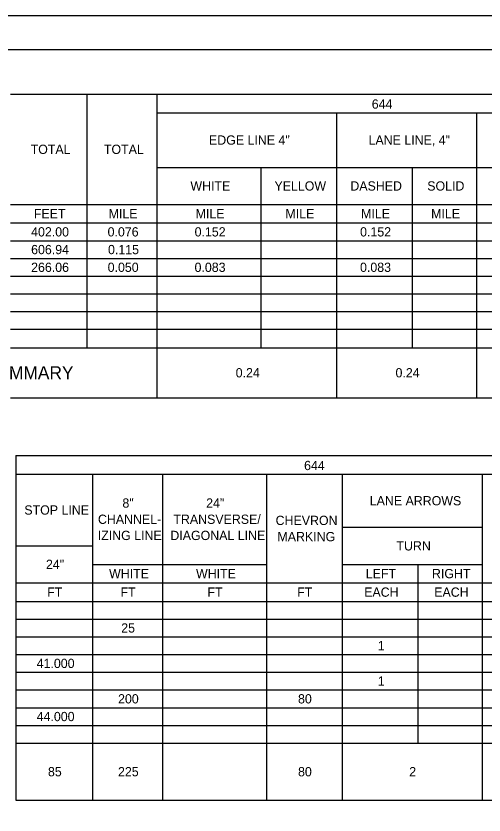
# Model space of a CAD drawing. Extents: x 0 to 53.1, y -5.3 to 22.
# Drawn here: x 7.93 to 14.91, y 10.09 to 22 of the extents above; entities that cross this region are included whole.
import ezdxf

# ---------------------------------------------------------------- set-up
doc = ezdxf.new("R2010")
doc.units = 0
for name, color, linetype in [('SH_Border', 7, 'Continuous'), ('SH_Cut_Line', 7, 'Continuous'), ('SH_Text', 7, 'Continuous')]:
    doc.layers.add(name, color=color, linetype=linetype)

msp = doc.modelspace()

# ---------------------------------------------------------------- linework, layer by layer
at = {"layer": 'SH_Border'}
msp.add_lwpolyline([(1.5, 21.5), (33.5, 21.5), (33.5, 0.5), (1.5, 0.5)], close=True, dxfattribs=at)
at = {"layer": 'SH_Cut_Line'}
msp.add_lwpolyline([(0, 0), (34, 0), (34, 22), (0, 22)], close=True, dxfattribs=at)
at = {"layer": 'SH_Text'}
for p, q in [((7.85, 20.835), (30.482, 20.835)), ((8.99, 20.835), (8.99, 20.019)), ((10.034, 20.835), (10.034, 20.019)), ((10.034, 20.559), (27.602, 20.559)), ((12.71, 20.559), (12.71, 20.019)), ((14.798, 20.559), (14.798, 20.019)), ((8.99, 20.019), (8.99, 19.467)), ((10.034, 20.019), (10.034, 19.467)), ((12.71, 20.019), (12.71, 19.467)), ((14.798, 20.019), (14.798, 19.467)), ((10.034, 19.743), (27.602, 19.743)), ((11.582, 19.743), (11.582, 19.467)), ((13.838, 19.743), (13.838, 19.467)), ((8.99, 19.467), (8.99, 19.191)), ((10.034, 19.467), (10.034, 19.191)), ((11.582, 19.467), (11.582, 19.191)), ((12.71, 19.467), (12.71, 19.191)), ((13.838, 19.467), (13.838, 19.191)), ((14.798, 19.467), (14.798, 19.191)), ((7.85, 19.191), (27.602, 19.191)), ((8.99, 19.191), (8.99, 17.859)), ((10.034, 19.191), (10.034, 17.859)), ((11.582, 19.191), (11.582, 17.859)), ((12.71, 19.191), (12.71, 17.859)), ((13.838, 19.191), (13.838, 17.859)), ((14.798, 19.191), (14.798, 17.859)), ((7.85, 18.915), (30.482, 18.915)), ((7.85, 18.651), (30.482, 18.651)), ((7.85, 18.387), (30.482, 18.387)), ((7.85, 18.123), (30.482, 18.123)), ((7.85, 17.859), (30.482, 17.859)), ((8.99, 17.859), (8.99, 17.595)), ((10.034, 17.859), (10.034, 17.595)), ((11.582, 17.859), (11.582, 17.595)), ((12.71, 17.859), (12.71, 17.595)), ((13.838, 17.859), (13.838, 17.595)), ((14.798, 17.859), (14.798, 17.595)), ((7.85, 17.595), (30.482, 17.595)), ((8.99, 17.595), (8.99, 17.055)), ((10.034, 17.595), (10.034, 16.311)), ((11.582, 17.595), (11.582, 17.055)), ((12.71, 17.595), (12.71, 16.311)), ((13.838, 17.595), (13.838, 17.055)), ((14.798, 17.595), (14.798, 16.311)), ((7.85, 17.331), (30.482, 17.331)), ((7.85, 17.055), (30.482, 17.055)), ((7.85, 16.311), (30.482, 16.311)), ((7.933, 15.448), (27.685, 15.448)), ((7.933, 15.448), (7.933, 15.172)), ((7.933, 15.172), (27.685, 15.172)), ((7.933, 15.172), (7.933, 14.656)), ((9.073, 15.172), (9.073, 14.656)), ((10.117, 15.172), (10.117, 14.656)), ((11.665, 15.172), (11.665, 14.656)), ((12.793, 15.172), (12.793, 14.656)), ((14.881, 15.172), (14.881, 14.656)), ((7.933, 14.656), (7.933, 14.38)), ((9.073, 14.656), (9.073, 14.38)), ((10.117, 14.656), (10.117, 14.38)), ((11.665, 14.656), (11.665, 14.38)), ((12.793, 14.656), (12.793, 14.38)), ((14.881, 14.656), (14.881, 14.38)), ((7.933, 14.38), (7.933, 14.104)), ((9.073, 14.38), (9.073, 14.104)), ((10.117, 14.38), (10.117, 14.104)), ((11.665, 14.38), (11.665, 14.104)), ((12.793, 14.38), (14.881, 14.38)), ((12.793, 14.38), (12.793, 14.104)), ((14.881, 14.38), (14.881, 14.104)), ((7.933, 14.104), (9.073, 14.104)), ((7.933, 14.104), (7.933, 13.828)), ((9.073, 14.104), (9.073, 13.828)), ((10.117, 14.104), (10.117, 13.828)), ((11.665, 14.104), (11.665, 13.828)), ((12.793, 14.104), (12.793, 13.828)), ((14.881, 14.104), (14.881, 13.828)), ((7.933, 13.828), (7.933, 13.552)), ((9.073, 13.828), (11.665, 13.828)), ((9.073, 13.828), (9.073, 13.552)), ((10.117, 13.828), (10.117, 13.552)), ((11.665, 13.828), (11.665, 13.552)), ((12.793, 13.828), (14.881, 13.828)), ((12.793, 13.828), (12.793, 13.552)), ((13.921, 13.828), (13.921, 13.552)), ((14.881, 13.828), (14.881, 13.552)), ((7.933, 13.552), (27.685, 13.552)), ((7.933, 13.552), (7.933, 12.748)), ((9.073, 13.552), (9.073, 12.748)), ((10.117, 13.552), (10.117, 12.748)), ((11.665, 13.552), (11.665, 12.748)), ((12.793, 13.552), (12.793, 12.748)), ((13.921, 13.552), (13.921, 12.748)), ((14.881, 13.552), (14.881, 12.748)), ((7.933, 13.276), (27.685, 13.276)), ((7.933, 13.012), (27.685, 13.012)), ((7.933, 12.748), (27.685, 12.748)), ((7.933, 12.748), (7.933, 12.484)), ((9.073, 12.748), (9.073, 12.484)), ((10.117, 12.748), (10.117, 12.484)), ((11.665, 12.748), (11.665, 12.484)), ((12.793, 12.748), (12.793, 12.484)), ((13.921, 12.748), (13.921, 12.484)), ((14.881, 12.748), (14.881, 12.484)), ((7.933, 12.484), (27.685, 12.484)), ((7.933, 12.484), (7.933, 12.22)), ((9.073, 12.484), (9.073, 12.22)), ((10.117, 12.484), (10.117, 12.22)), ((11.665, 12.484), (11.665, 12.22)), ((12.793, 12.484), (12.793, 12.22)), ((13.921, 12.484), (13.921, 12.22)), ((14.881, 12.484), (14.881, 12.22)), ((7.933, 12.22), (27.685, 12.22)), ((7.933, 12.22), (7.933, 11.956)), ((9.073, 12.22), (9.073, 11.956)), ((10.117, 12.22), (10.117, 11.956)), ((11.665, 12.22), (11.665, 11.956)), ((12.793, 12.22), (12.793, 11.956)), ((13.921, 12.22), (13.921, 11.956)), ((14.881, 12.22), (14.881, 11.956)), ((7.933, 11.956), (27.685, 11.956)), ((7.933, 11.956), (7.933, 10.312)), ((9.073, 11.956), (9.073, 10.312)), ((10.117, 11.956), (10.117, 10.312)), ((11.665, 11.956), (11.665, 10.312)), ((12.793, 11.956), (12.793, 10.312)), ((13.921, 11.956), (13.921, 11.164)), ((14.881, 11.956), (14.881, 10.312)), ((7.933, 11.692), (27.685, 11.692)), ((7.933, 11.428), (27.685, 11.428)), ((7.933, 11.164), (27.685, 11.164)), ((7.933, 10.312), (27.685, 10.312))]:
    msp.add_line(p, q, dxfattribs=at)

# ---------------------------------------------------------------- texts
for s, height, p in [('644', 0.138, (13.236, 20.619)), ('EDGE LINE 4"', 0.138, (10.81, 20.082)), ('LANE LINE, 4"', 0.138, (13.188, 20.082)), ('TOTAL', 0.138, (8.152, 19.944)), ('TOTAL', 0.138, (9.244, 19.944)), ('WHITE', 0.138, (10.533, 19.398)), ('YELLOW', 0.138, (11.786, 19.398)), ('DASHED', 0.138, (12.917, 19.398)), ('SOLID', 0.138, (14.063, 19.398)), ('FEET', 0.138, (8.2, 18.984)), ('MILE', 0.138, (9.315, 18.984)), ('MILE', 0.138, (10.611, 18.984)), ('MILE', 0.138, (11.949, 18.984)), ('MILE', 0.138, (13.077, 18.984)), ('MILE', 0.138, (14.121, 18.984)), ('402.00', 0.138, (8.159, 18.714)), ('0.076', 0.138, (9.299, 18.714)), ('0.152', 0.138, (10.596, 18.714)), ('0.152', 0.138, (13.062, 18.714)), ('606.94', 0.138, (8.159, 18.45)), ('0.115', 0.138, (9.305, 18.45)), ('266.06', 0.138, (8.159, 18.186)), ('0.050', 0.138, (9.3, 18.186)), ('0.083', 0.138, (10.595, 18.186)), ('0.083', 0.138, (13.061, 18.186)), ('TOTALS CARRIED TO GENERAL SUMMARY', 0.1932, (3.422, 16.587)), ('0.24', 0.138, (11.208, 16.614)), ('0.24', 0.138, (13.59, 16.614)), ('644', 0.138, (12.227, 15.232)), ('8"', 0.138, (9.52, 14.673)), ('24" ', 0.138, (10.768, 14.673)), ('LANE ARROWS', 0.138, (13.206, 14.707)), ('STOP LINE', 0.138, (8.058, 14.569)), ('CHANNEL-', 0.138, (9.155, 14.431)), ('TRANSVERSE/ ', 0.138, (10.279, 14.431)), ('CHEVRON ', 0.138, (11.803, 14.414)), ('IZING LINE', 0.138, (9.152, 14.19)), ('DIAGONAL LINE', 0.138, (10.234, 14.19)), ('MARKING', 0.138, (11.83, 14.172)), ('TURN', 0.138, (13.604, 14.035)), ('24"', 0.138, (8.38, 13.759)), ('WHITE', 0.138, (9.321, 13.621)), ('WHITE', 0.138, (10.617, 13.621)), ('LEFT', 0.138, (13.147, 13.621)), ('RIGHT', 0.138, (14.133, 13.621)), ('FT', 0.138, (8.399, 13.345)), ('FT', 0.138, (9.491, 13.345)), ('FT', 0.138, (10.787, 13.345)), ('FT', 0.138, (12.125, 13.345)), ('EACH', 0.138, (13.123, 13.345)), ('EACH', 0.138, (14.167, 13.345)), ('25', 0.138, (9.502, 12.811)), ('1', 0.138, (13.325, 12.547)), ('41.000', 0.138, (8.242, 12.283)), ('1', 0.138, (13.325, 12.019)), ('200', 0.138, (9.455, 11.755)), ('80', 0.138, (12.137, 11.755)), ('44.000', 0.138, (8.242, 11.491)), ('85', 0.138, (8.41, 10.669)), ('225', 0.138, (9.454, 10.669)), ('80', 0.138, (12.137, 10.669)), ('2', 0.138, (13.794, 10.669))]:
    msp.add_text(s, height=height, dxfattribs=at).set_placement(p)

doc.saveas('drawing.dxf')
